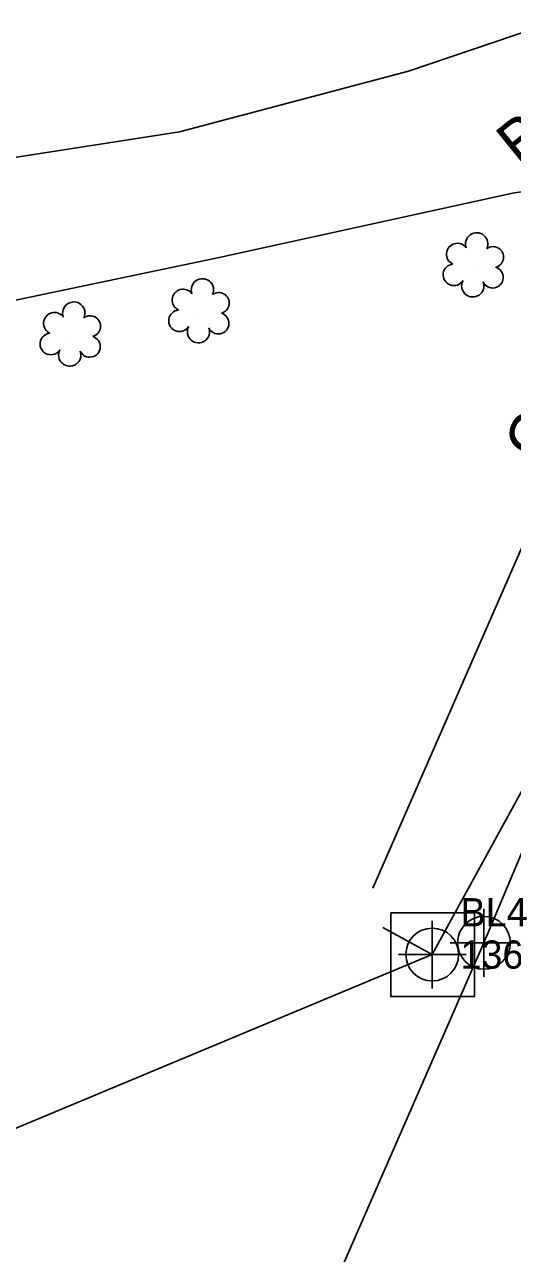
# Model space of a CAD drawing. Extents: x 1435573 to 1437263, y 981340 to 982884.
# Drawn here: x 1435804.6 to 1435847.8, y 981720.6 to 981829.5 of the extents above; entities that cross this region are included whole.
import ezdxf

# ---------------------------------------------------------------- set-up
doc = ezdxf.new("R2010")
doc.units = 0
for name, color, linetype in [('Cogo Default Point CELL', 7, 'Continuous'), ('COGO Default Point Elevation', 7, 'Continuous'), ('COGO Default Point Number', 7, 'Continuous'), ('CTL Supplemental Horizontal and Vertical CELL', 7, 'Continuous'), ('Exist Horizontal Baseline Alignment', 7, 'Continuous'), ('Exist Horizontal Baseline Alignment Station Label', 7, 'Continuous'), ('Exist Horizontal Baseline Alignment Tick small', 7, 'Continuous'), ('Exist Right of Way Line', 7, 'Continuous'), ('Exist Roads EOP', 7, 'Continuous'), ('Exist Roads EOP Cogo Point CELL', 7, 'Continuous'), ('Exist Roads EOP Other', 7, 'Continuous'), ('Exist Roads EOP Text', 7, 'Continuous'), ('Exist Structure Minor Drop Inlet Text', 7, 'Continuous'), ('Exist Vegetation Shrub CELL', 7, 'Continuous')]:
    doc.layers.add(name, color=color, linetype=linetype)

# ---------------------------------------------------------------- blocks, each defined once
blk = doc.blocks.new('CTL SUPPLEMENTAL HORIZONTAL AND VERTICAL')
at = {"layer": 'CTL Supplemental Horizontal and Vertical CELL'}
blk.add_line((0, 0), (0, 0), dxfattribs=at)
blk.add_lwpolyline([(-0.0735, 0.074), (0.07475, 0.074), (0.07475, -0.0745), (-0.0735, -0.0745)], close=True, dxfattribs=at)

msp = doc.modelspace()

# ---------------------------------------------------------------- linework, layer by layer
at = {"layer": 'Cogo Default Point CELL'}
for points in [[(1435840.71, 981750.05), (1435840.71, 981747.05)], [(1435837.71, 981747.05), (1435840.71, 981747.05)], [(1435840.71, 981747.05), (1435843.71, 981747.05)], [(1435840.71, 981747.05), (1435840.71, 981744.05)]]:
    msp.add_lwpolyline(points, dxfattribs=at)
msp.add_circle((1435840.71, 981747.05), 2.34, dxfattribs=at)
at = {"layer": 'Exist Horizontal Baseline Alignment'}
msp.add_line((1435840.71, 981747.05), (1436220.79, 982442.59), dxfattribs=at)
at = {"layer": 'Exist Horizontal Baseline Alignment Station Label'}
msp.add_line((1435840.71, 981747.05), (1435784.44, 981723.56), dxfattribs=at)
at = {"layer": 'Exist Horizontal Baseline Alignment Tick small'}
msp.add_line((1435840.71, 981747.05), (1435836.33, 981749.45), dxfattribs=at)
at = {"layer": 'Exist Right of Way Line'}
msp.add_line((1435835.44, 981752.92), (1435892.66, 981883.95), dxfattribs=at)
at = {"layer": 'Exist Roads EOP'}
msp.add_line((1435866.4, 981798.52), (1435845.29, 981748.09), dxfattribs=at)
msp.add_lwpolyline([(1435822.36, 981695.64), (1435845.29, 981748.09)], dxfattribs=at)
at = {"layer": 'Exist Roads EOP Cogo Point CELL'}
msp.add_lwpolyline([(1435845.29, 981751.09), (1435845.29, 981745.09), (1435845.29, 981748.09), (1435848.29, 981748.09), (1435842.29, 981748.09)], dxfattribs=at)
msp.add_circle((1435845.29, 981748.09), 2.34, dxfattribs=at)
at = {"layer": 'Exist Roads EOP Other'}
for points in [[(1435894.69, 981862.87), (1435885.86, 981852.99), (1435875.39, 981842.31), (1435869.41, 981837.88), (1435855.42, 981831.03), (1435838.61, 981825.35), (1435818.32, 981819.97), (1435785.65, 981814.88), (1435762.77, 981812.3), (1435718.8, 981811.75), (1435695.28, 981812.98), (1435683.33, 981814.66), (1435680.68, 981814.69), (1435670.22, 981803.31)], [(1435787.32, 981801.59), (1435821.85, 981808.84), (1435847.97, 981814.55), (1435855.94, 981815.63), (1435860.64, 981814.32), (1435864.43, 981811.33), (1435867.47, 981804.11)]]:
    msp.add_lwpolyline(points, dxfattribs=at)
at = {"layer": 'Exist Vegetation Shrub CELL'}
for p, q in [((1435844.43, 981807.99), (1435844.43, 981807.99)), ((1435820.13, 981803.92), (1435820.13, 981803.92)), ((1435808.74, 981801.86), (1435808.74, 981801.86))]:
    msp.add_line(p, q, dxfattribs=at)
for centre, radius, start, end in [((1435844.65, 981810.03), 0.99, 334.8391, 200.4717), ((1435842.94, 981809.12), 0.968, 35.8908, 245.4216), ((1435846.1, 981808.86), 0.929, 284.4567, 126.0861), ((1435842.63, 981807.29), 0.955, 95.1099, 327.9534), ((1435846.06, 981807.06), 0.937, 204.9913, 73.4601), ((1435820.36, 981805.96), 0.99, 334.8391, 200.4717), ((1435844.3, 981806.31), 0.984, 151.2797, 21.387), ((1435818.65, 981805.05), 0.968, 35.8908, 245.4216), ((1435821.81, 981804.79), 0.929, 284.4567, 126.0861), ((1435808.97, 981803.9), 0.99, 334.8391, 200.4717), ((1435818.33, 981803.22), 0.955, 95.1099, 327.9534), ((1435807.26, 981802.99), 0.968, 35.8908, 245.4216), ((1435810.41, 981802.73), 0.929, 284.4567, 126.0861), ((1435821.77, 981802.99), 0.937, 204.9913, 73.4601), ((1435806.94, 981801.16), 0.955, 95.1099, 327.9534), ((1435810.38, 981800.93), 0.937, 204.9913, 73.4601), ((1435820.01, 981802.24), 0.984, 151.2797, 21.387), ((1435808.61, 981800.18), 0.984, 151.2797, 21.387)]:
    msp.add_arc(centre, radius, start, end, dxfattribs=at)

# ---------------------------------------------------------------- block references
at = {"layer": 'CTL Supplemental Horizontal and Vertical CELL', "xscale": 50, "yscale": 50}
msp.add_blockref('CTL SUPPLEMENTAL HORIZONTAL AND VERTICAL', (1435840.71, 981747.05), dxfattribs=at)

# ---------------------------------------------------------------- texts
at = {"layer": 'COGO Default Point Elevation'}
msp.add_text('1363.57', height=2.5, dxfattribs=at).set_placement((1435843.21, 981745.8))
at = {"layer": 'COGO Default Point Number'}
msp.add_text('BL4', height=2.5, dxfattribs=at).set_placement((1435843.21, 981749.55))
at = {"layer": 'Exist Roads EOP Text'}
msp.add_text('BST', height=4, rotation=38.9453, dxfattribs=at).set_placement((1435848.53, 981816.68))
at = {"layer": 'Exist Structure Minor Drop Inlet Text'}
msp.add_text('CB', height=4, rotation=67.9565, dxfattribs=at).set_placement((1435850.69, 981790.54))

doc.saveas('drawing.dxf')
